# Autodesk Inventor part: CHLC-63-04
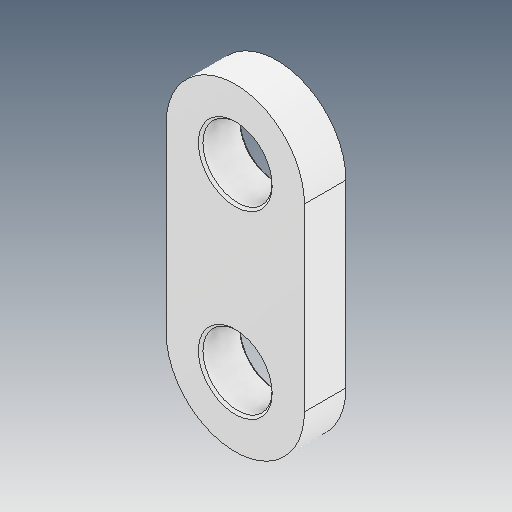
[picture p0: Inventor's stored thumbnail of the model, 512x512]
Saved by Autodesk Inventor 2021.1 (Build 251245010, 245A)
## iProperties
Created: 2021-05
Part Number: CHLC-63-04
Material: Ogólny
Document SubType Name: Modeling
Designer: user
Density: 1 g/cm^3
Appearance: Domyślna
Author: user
Revision Number: ÈÎºÎ
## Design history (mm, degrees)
feature "ÊäÈë1"
node "Bryła1"
